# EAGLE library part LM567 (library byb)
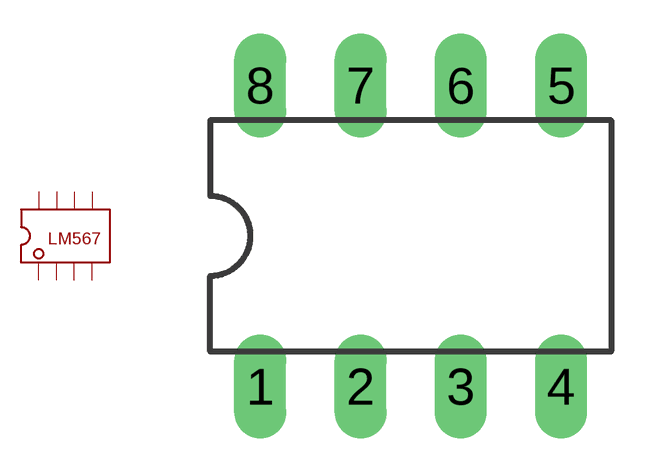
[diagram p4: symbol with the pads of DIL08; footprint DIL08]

Designator prefix -

## LM567  [DIL08]
1  P$1
2  P$2
3  P$3
4  P$4
5  P$5
6  P$6
7  P$7
8  P$8

## Footprint DIL08 (pad centres in mm)
Dual In Line Package
drill 0.813 pad 1.27 long: 1 -3.81,-3.81; 2 -1.27,-3.81; 3 1.27,-3.81; 4 3.81,-3.81; 5 3.81,3.81; 6 1.27,3.81; 7 -1.27,3.81; 8 -3.81,3.81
